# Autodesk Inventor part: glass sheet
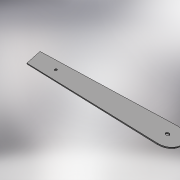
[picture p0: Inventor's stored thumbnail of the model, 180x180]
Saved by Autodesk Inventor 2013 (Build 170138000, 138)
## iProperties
Shininess: 64.0
Length Units: 11269
Angle Units: 11279
Time Units: 11290
Mass Units: 11283
Length Display Precision: 3
Angle Display Precision: 2
Compacted: True
Part Number: glass sheet
Document SubType Name: Листовой материал
Created: 2004-12
Material: Stainless Steel, 440C
Designer: =<Author>
Manufacturer: Standard
Standards Organization: Custom
Description: =<Part Number>
Density: 7.75 g/cm^3
Sheet Metal Rule: По умолчанию
Mass: 1357.52 g
Surface Area: 928.61 cm^2
Volume: 175.164 cm^3
Density: 0.0
Volumn: 0.0
Area: 0.0
PropertySet Name: Model Information
Control State: 0
Master: False
Checked Out: False
Checked Out Date: 2008-10-15
Last Check In Date: 2008-10-15
Толщина: 4.000 mm
Радиус_гибки: 4.000 mm
Ширина_просечки: 4.000 mm
Глубина_просечки: 2.000 mm
Размер_высечки: 16.000 mm
Минимальный_остаток: 8.000 mm
Радиус_перехода: 4.000 mm
JacobiRadiusSize: 4.000 mm
GapSize: 4.000 mm
d0: 80.000 mm
d2: 537.000 mm
d3: 11.000 mm
d4: 4.000 mm
d5: 400.000 mm
d6: 25.00 deg
Author: PVitaliy
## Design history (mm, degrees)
node "Грань1"
body "Solid1"
sketch "Эскиз1"
  geometry: L1 (0, 0)-(537, 0); L2 (537, 80)-(0, 80); L3 (0, 80)-(0, 0); L4 (537, 40)-(137, 40); L5 (0, 80)-(37.305, 0); C1 r 5.5 at (537, 40); C2 r 5.5 at (137, 40); A1 r 40 centre (537, 40) between (537, 0) and (537, 80)
  constraints: 10 end point, 3 centre point, 2 coincident, 2 point on circle, 2 tangent, 1 equal radius, 1 horizontal, 1 parallel, 1 perpendicular, 1 point on line, 1 vertical, 1 other
  dimensions: "d0" = 80 distance between parallel lines of L1 L2; "d2" = 537 distance from line of A1.centre L3; "d3" = 11 diameter of C1; "d5" = 400 distance of L4.start L4.end; "d6" = 25 deg angle of L3 L5
feature "Пластина1" dims "Толщина" = 4
other parameters: "Радиус_гибки" = 4 (= Толщина), "Ширина_просечки" = 4 (= Толщина), "Глубина_просечки" = 2 (= 0.5 x Толщина), "Размер_высечки" = 16 (= 4 x Толщина), "Зазор_стыка" = 0.01, "Минимальный_остаток" = 8 (= 2 x Толщина), "Радиус_перехода" = 4 (= Радиус_гибки), "d4" = 4 (= Радиус_гибки), "JacobiRadiusSize" = 4 (= Толщина), "GapSize" = 4 (= Толщина)
